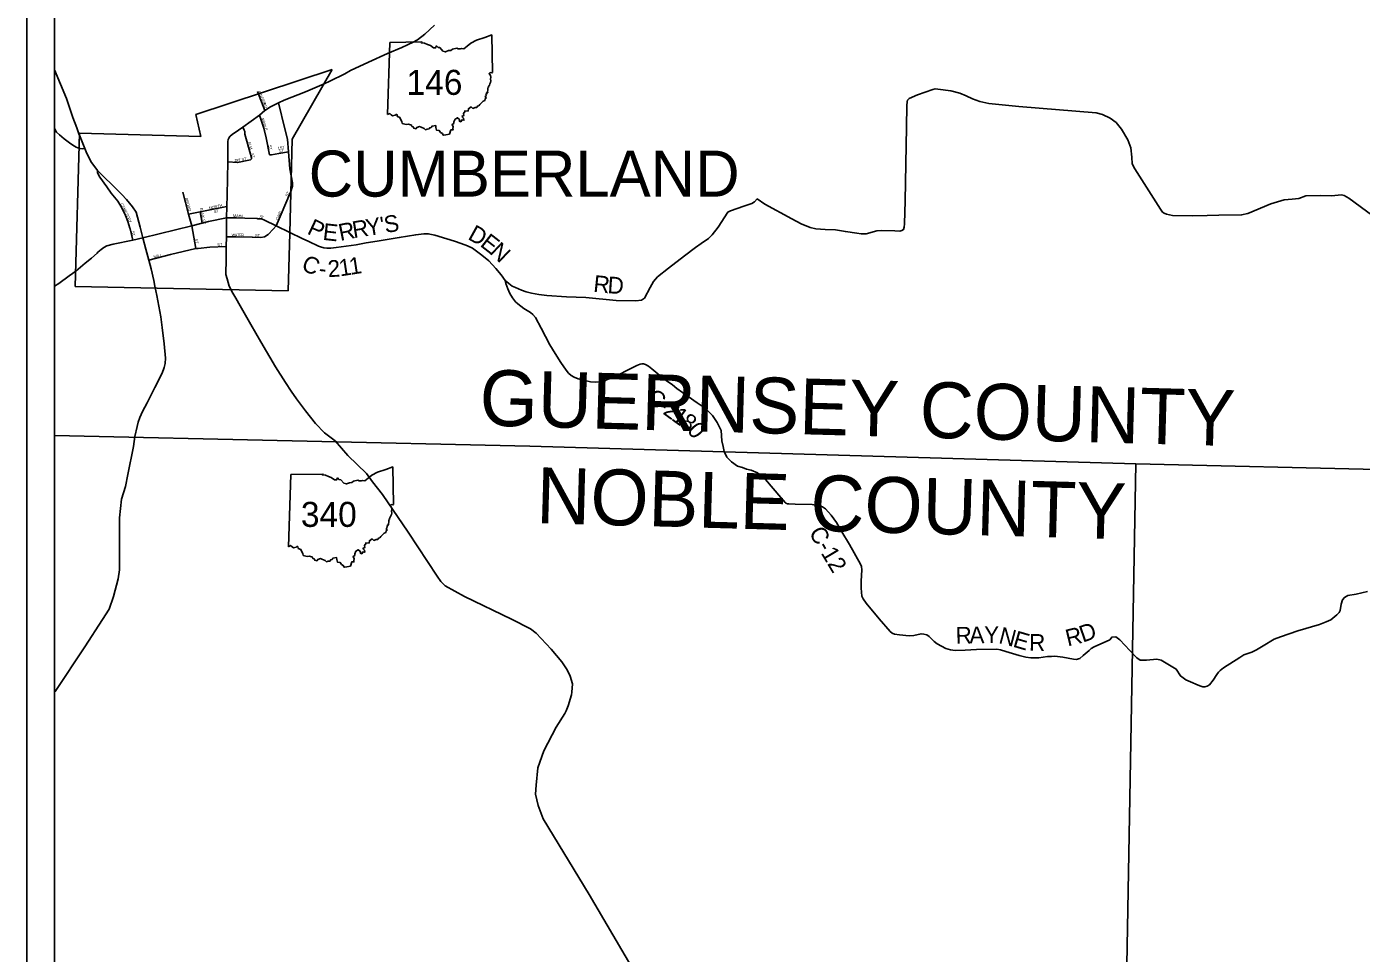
# Model space of a CAD drawing. Extents: x -452339 to 6403467, y -1 to 1814750.
# Drawn here: x -403540 to -379658, y 1620054 to 1636629 of the extents above; entities that cross this region are included whole.
import ezdxf

# ---------------------------------------------------------------- set-up
doc = ezdxf.new("R2010")
doc.units = 0
for name, color, linetype in [('Default', 7, 'Continuous'), ('GM_X_Adjacent_County_Text', 7, 'Continuous'), ('GM_X_County', 7, 'Continuous'), ('GM_X_County_Road', 7, 'Continuous'), ('GM_X_County_ROW', 7, 'Continuous'), ('GM_X_Minor_Lake', 7, 'Continuous'), ('GM_X_Minor_River', 7, 'Continuous'), ('GM_X_Minor_River_Text', 7, 'Continuous'), ('GM_X_Section_Text', 7, 'Continuous')]:
    doc.layers.add(name, color=color, linetype=linetype)

msp = doc.modelspace()

# ---------------------------------------------------------------- linework, layer by layer
at = {"layer": 'Default'}
for p, q in [((-403040, 1603979), (-403040, 1661357)), ((-397082, 1635056), (-397041, 1636348)), ((-398854, 1627328), (-398813, 1628619))]:
    msp.add_line(p, q, dxfattribs=at)
msp.add_lwpolyline([(-403540, 1661857), (-345163, 1661857), (-345163, 1603479), (-403540, 1603479)], close=True, dxfattribs=at)
for points in [[(-397041, 1636348), (-396468, 1636356), (-396477, 1636340), (-396423, 1636337), (-396366, 1636309), (-396317, 1636292), (-396258, 1636251), (-396222, 1636251), (-396207, 1636285), (-396180, 1636259), (-396148, 1636255), (-396092, 1636193), (-396046, 1636179), (-395990, 1636201), (-395950, 1636204), (-395919, 1636225), (-395841, 1636243), (-395819, 1636232), (-395777, 1636235), (-395756, 1636242), (-395720, 1636235), (-395656, 1636282), (-395591, 1636337), (-395489, 1636390), (-395339, 1636439), (-395219, 1636483), (-395202, 1635813)], [(-395202, 1635813), (-395219, 1635804), (-395247, 1635808), (-395265, 1635790), (-395242, 1635758), (-395232, 1635725), (-395241, 1635689), (-395232, 1635659), (-395238, 1635633), (-395255, 1635608), (-395261, 1635584), (-395276, 1635559), (-395275, 1635545), (-395289, 1635534), (-395286, 1635492), (-395293, 1635469), (-395291, 1635449), (-395314, 1635444), (-395308, 1635427), (-395323, 1635414), (-395320, 1635392), (-395336, 1635378), (-395320, 1635350), (-395333, 1635341), (-395344, 1635307), (-395373, 1635300), (-395430, 1635238), (-395451, 1635214), (-395474, 1635208), (-395487, 1635184), (-395515, 1635184), (-395559, 1635167), (-395586, 1635196), (-395635, 1635161), (-395641, 1635120), (-395702, 1635122), (-395700, 1635101), (-395713, 1635096), (-395726, 1635075), (-395719, 1635039), (-395748, 1635030), (-395744, 1635009), (-395725, 1634996), (-395717, 1634956), (-395748, 1634964), (-395773, 1634930), (-395799, 1634938), (-395791, 1634966), (-395834, 1635001), (-395875, 1634974), (-395897, 1634929), (-395897, 1634899), (-395928, 1634881), (-395908, 1634840), (-395912, 1634811), (-395911, 1634783), (-395950, 1634784), (-395973, 1634710)], [(-394980, 1632091), (-394910, 1632034), (-394855, 1631990), (-394796, 1631963), (-394688, 1631915), (-394605, 1631886), (-394505, 1631861), (-394376, 1631842), (-394235, 1631824), (-393879, 1631797), (-393536, 1631784), (-392994, 1631731), (-392637, 1631723), (-392539, 1631738), (-392486, 1631775), (-392386, 1631964), (-392325, 1632073), (-392252, 1632156), (-392057, 1632308), (-391766, 1632529), (-391573, 1632682), (-391468, 1632751), (-391341, 1632842), (-391271, 1632905), (-391169, 1633041), (-390994, 1633313), (-390946, 1633337), (-390708, 1633422), (-390567, 1633468), (-390519, 1633498), (-390470, 1633549), (-390333, 1633455), (-389848, 1633194), (-389684, 1633105), (-389519, 1633036), (-389419, 1633014), (-389249, 1633003), (-389068, 1632994), (-388888, 1632963), (-388687, 1632936), (-388607, 1632925), (-388517, 1632926), (-388330, 1632978), (-388238, 1632981), (-388004, 1632978), (-387918, 1632973), (-387881, 1632984), (-387849, 1632999), (-387838, 1633041), (-387831, 1633105), (-387822, 1633512), (-387795, 1634833), (-387788, 1635222), (-387785, 1635286), (-387778, 1635316), (-387746, 1635347), (-387599, 1635410), (-387325, 1635507), (-387281, 1635516), (-387233, 1635513), (-387005, 1635481), (-386840, 1635440), (-386729, 1635392), (-386614, 1635338), (-386482, 1635292), (-386321, 1635257), (-385784, 1635201), (-384400, 1635087), (-384286, 1635061), (-384149, 1634993), (-384047, 1634917), (-383947, 1634797), (-383833, 1634605), (-383783, 1634465), (-383762, 1634298), (-383757, 1634174), (-383712, 1634084), (-383253, 1633366), (-383218, 1633313), (-383187, 1633295), (-383145, 1633276), (-383039, 1633254), (-382673, 1633247), (-382417, 1633253), (-382209, 1633258), (-381801, 1633263), (-381686, 1633287), (-381275, 1633459), (-381040, 1633533), (-380896, 1633542), (-380777, 1633554), (-380650, 1633603), (-380382, 1633611), (-380194, 1633603), (-380012, 1633619), (-379964, 1633611), (-379883, 1633563), (-379247, 1633100)], [(-395973, 1634710), (-396040, 1634696), (-396086, 1634687), (-396102, 1634721), (-396136, 1634739), (-396157, 1634772), (-396205, 1634777), (-396216, 1634824), (-396221, 1634861), (-396287, 1634852), (-396304, 1634829), (-396327, 1634823), (-396341, 1634800), (-396372, 1634798), (-396406, 1634787), (-396428, 1634809), (-396484, 1634833), (-396509, 1634844), (-396561, 1634826), (-396572, 1634804), (-396613, 1634814), (-396623, 1634838), (-396648, 1634845), (-396653, 1634871), (-396707, 1634885), (-396748, 1634879), (-396820, 1634900), (-396825, 1634934), (-396849, 1634975), (-396862, 1635004), (-396907, 1635025), (-396917, 1635060), (-396931, 1635059), (-396945, 1635045), (-396996, 1635038), (-397016, 1635052), (-397044, 1635076), (-397082, 1635056)], [(-398833, 1632951), (-398612, 1632840), (-398494, 1632785), (-398320, 1632706), (-398283, 1632689), (-398224, 1632673), (-398169, 1632667), (-398096, 1632668), (-398005, 1632678), (-397644, 1632730), (-397466, 1632761), (-397270, 1632792), (-396873, 1632856), (-396578, 1632909), (-396434, 1632926), (-396353, 1632926), (-396234, 1632903), (-396020, 1632834), (-395885, 1632792), (-395768, 1632754), (-395655, 1632708), (-395562, 1632665), (-395493, 1632616), (-395398, 1632542), (-395272, 1632439), (-395144, 1632304), (-395052, 1632192), (-394980, 1632091)], [(-391057, 1629033), (-391076, 1629122), (-391099, 1629224), (-391112, 1629405), (-391182, 1629548), (-391268, 1629675), (-391363, 1629769), (-391434, 1629828), (-391545, 1629902), (-391706, 1630014), (-391909, 1630160), (-391985, 1630226), (-392095, 1630300), (-392244, 1630417), (-392352, 1630510), (-392414, 1630556), (-392464, 1630587), (-392502, 1630601), (-392532, 1630601), (-392564, 1630594), (-392623, 1630570), (-392691, 1630535), (-392787, 1630486), (-392951, 1630404), (-393117, 1630330), (-393222, 1630291), (-393284, 1630276), (-393354, 1630270), (-393451, 1630276), (-393553, 1630298), (-393673, 1630331), (-393745, 1630358), (-393798, 1630392), (-393843, 1630430), (-393884, 1630484), (-393981, 1630622), (-394083, 1630785), (-394177, 1630940), (-394331, 1631236), (-394436, 1631427), (-394481, 1631481), (-394523, 1631516), (-394645, 1631591), (-394752, 1631671), (-394793, 1631709), (-394849, 1631779), (-394895, 1631854), (-394929, 1631938), (-394969, 1632037), (-394980, 1632091)], [(-391057, 1629033), (-391010, 1628931), (-390928, 1628847), (-390821, 1628771), (-390733, 1628742), (-390658, 1628713), (-390578, 1628696), (-390465, 1628651), (-390404, 1628604), (-390321, 1628528), (-390047, 1628210), (-389968, 1628121), (-389953, 1628108), (-389927, 1628096), (-389901, 1628096), (-389787, 1628090), (-389487, 1628080), (-389357, 1628060), (-389298, 1628039), (-389248, 1628004), (-389142, 1627894), (-389047, 1627761), (-388951, 1627593), (-388815, 1627365), (-388617, 1627016), (-388600, 1626976), (-388597, 1626916), (-388605, 1626711), (-388607, 1626583), (-388604, 1626515), (-388593, 1626445), (-388570, 1626397), (-388521, 1626320), (-388284, 1626040), (-388086, 1625811), (-388051, 1625780), (-388011, 1625762), (-387921, 1625754), (-387751, 1625735), (-387667, 1625740), (-387535, 1625769), (-387487, 1625762), (-387435, 1625749), (-387388, 1625721), (-387358, 1625690), (-387301, 1625629), (-387246, 1625590), (-387093, 1625504), (-387010, 1625480), (-386924, 1625469), (-386746, 1625474), (-386646, 1625484), (-386542, 1625486), (-386179, 1625495), (-386112, 1625484), (-386018, 1625455), (-385783, 1625381), (-385660, 1625352), (-385570, 1625339), (-385426, 1625338), (-385272, 1625361), (-385202, 1625366), (-385144, 1625369), (-384996, 1625351), (-384807, 1625313), (-384759, 1625312), (-384696, 1625329), (-384633, 1625380), (-384530, 1625470), (-384491, 1625507), (-384439, 1625536), (-384155, 1625663), (-384154, 1625665)], [(-398813, 1628619), (-398240, 1628628), (-398249, 1628612), (-398195, 1628609), (-398138, 1628581), (-398089, 1628564), (-398030, 1628523), (-397995, 1628523), (-397980, 1628557), (-397952, 1628531), (-397920, 1628526), (-397864, 1628464), (-397818, 1628451), (-397763, 1628472), (-397722, 1628476), (-397692, 1628497), (-397613, 1628515), (-397591, 1628504), (-397549, 1628506), (-397528, 1628514), (-397492, 1628507), (-397429, 1628554), (-397363, 1628609), (-397261, 1628662), (-397111, 1628711), (-396991, 1628755), (-396974, 1628085)], [(-396974, 1628085), (-396991, 1628076), (-397019, 1628080), (-397037, 1628062), (-397014, 1628030), (-397004, 1627997), (-397013, 1627961), (-397004, 1627930), (-397010, 1627905), (-397027, 1627880), (-397033, 1627856), (-397048, 1627831), (-397047, 1627817), (-397061, 1627806), (-397058, 1627764), (-397065, 1627741), (-397063, 1627721), (-397086, 1627715), (-397081, 1627699), (-397095, 1627686), (-397092, 1627664), (-397108, 1627650), (-397092, 1627622), (-397105, 1627613), (-397116, 1627579), (-397145, 1627572), (-397203, 1627509), (-397223, 1627486), (-397246, 1627480), (-397259, 1627455), (-397288, 1627455), (-397331, 1627439), (-397359, 1627467), (-397407, 1627433), (-397413, 1627392), (-397474, 1627394), (-397472, 1627373), (-397486, 1627367), (-397498, 1627347), (-397491, 1627311), (-397520, 1627301), (-397516, 1627281), (-397498, 1627268), (-397490, 1627228), (-397520, 1627236), (-397545, 1627202), (-397571, 1627210), (-397563, 1627238), (-397606, 1627273), (-397648, 1627245), (-397669, 1627201), (-397669, 1627171), (-397700, 1627153), (-397680, 1627111), (-397684, 1627082), (-397684, 1627055), (-397722, 1627056), (-397745, 1626982)], [(-397745, 1626982), (-397812, 1626968), (-397858, 1626959), (-397875, 1626993), (-397908, 1627011), (-397930, 1627044), (-397977, 1627049), (-397988, 1627096), (-397994, 1627133), (-398059, 1627124), (-398076, 1627101), (-398100, 1627095), (-398113, 1627071), (-398145, 1627070), (-398178, 1627058), (-398201, 1627081), (-398256, 1627104), (-398281, 1627116), (-398333, 1627098), (-398344, 1627076), (-398385, 1627086), (-398395, 1627110), (-398420, 1627117), (-398426, 1627143), (-398479, 1627157), (-398520, 1627151), (-398592, 1627172), (-398597, 1627206), (-398622, 1627247), (-398634, 1627276), (-398680, 1627297), (-398689, 1627331), (-398704, 1627330), (-398717, 1627317), (-398768, 1627310), (-398788, 1627324), (-398817, 1627348), (-398854, 1627328)], [(-384154, 1625665), (-384124, 1625707), (-384053, 1625716), (-383980, 1625664), (-383797, 1625468), (-383676, 1625341), (-383614, 1625298), (-383502, 1625298), (-383317, 1625315), (-383241, 1625298), (-383147, 1625244), (-382968, 1625137), (-382896, 1625016), (-382797, 1624948), (-382670, 1624890), (-382616, 1624869), (-382549, 1624836), (-382495, 1624819), (-382457, 1624818), (-382415, 1624835), (-382376, 1624859), (-382311, 1624941), (-382241, 1625040), (-382211, 1625083), (-382186, 1625115), (-382123, 1625160), (-381834, 1625348), (-381757, 1625393), (-381614, 1625440), (-381532, 1625481), (-381352, 1625589), (-381275, 1625636), (-381219, 1625671), (-381106, 1625717), (-380794, 1625823), (-380408, 1625936), (-380285, 1625982), (-380205, 1626022), (-380095, 1626108), (-380056, 1626149), (-380034, 1626185), (-380018, 1626302), (-379992, 1626380), (-379960, 1626421), (-379899, 1626452), (-379747, 1626481), (-379546, 1626525)]]:
    msp.add_lwpolyline(points, dxfattribs=at)
at = {"layer": 'GM_X_County_Road'}
for points in [[(-398114, 1635658), (-397845, 1635785), (-397746, 1635847), (-397421, 1635995), (-397081, 1636148), (-396830, 1636256), (-396624, 1636353), (-396548, 1636392), (-396417, 1636498), (-396242, 1636658)], [(-402600, 1634695), (-402643, 1634820), (-402714, 1635003), (-402825, 1635344), (-403040, 1635856)], [(-399898, 1634672), (-399864, 1634699), (-399749, 1634781), (-399672, 1634831), (-399373, 1635046), (-399279, 1635129), (-399179, 1635195), (-399034, 1635265), (-398931, 1635316), (-398554, 1635464), (-398218, 1635608), (-398114, 1635658)], [(-401464, 1632852), (-401464, 1632852), (-401510, 1633046), (-401583, 1633311), (-401646, 1633410), (-401756, 1633541), (-401836, 1633625), (-401988, 1633778), (-402180, 1633964), (-402273, 1634060), (-402319, 1634121), (-402379, 1634203), (-402427, 1634291), (-402475, 1634394), (-402502, 1634450), (-402598, 1634689), (-402600, 1634695)], [(-399965, 1633212), (-399958, 1633416), (-399951, 1633615), (-399938, 1634210), (-399939, 1634573), (-399933, 1634613), (-399925, 1634637), (-399905, 1634666), (-399898, 1634672)], [(-401464, 1632852), (-400587, 1633065), (-400425, 1633112), (-400398, 1633118), (-400284, 1633147), (-399965, 1633212)], [(-399965, 1633212), (-399965, 1632870), (-399968, 1632698), (-399970, 1632559), (-399969, 1632462)], [(-402266, 1632594), (-402205, 1632642), (-402158, 1632678), (-402104, 1632707), (-401990, 1632741), (-401641, 1632810), (-401464, 1632852)], [(-401246, 1631990), (-401266, 1632087), (-401315, 1632298), (-401355, 1632452), (-401407, 1632652), (-401464, 1632852)], [(-403040, 1631989), (-402965, 1632036), (-402779, 1632174), (-402663, 1632258), (-402492, 1632402), (-402383, 1632491), (-402282, 1632581), (-402266, 1632594)], [(-399969, 1632462), (-399969, 1632424), (-399974, 1632250), (-399974, 1632194), (-399953, 1632118), (-399915, 1631987)], [(-401606, 1629296), (-401565, 1629475), (-401547, 1629555), (-401517, 1629640), (-401467, 1629749), (-401385, 1629903), (-401245, 1630175), (-401118, 1630432), (-401081, 1630532), (-401061, 1630604), (-401058, 1630701), (-401078, 1630957), (-401113, 1631250), (-401141, 1631441), (-401211, 1631820), (-401246, 1631990)], [(-399915, 1631987), (-399914, 1631984), (-399869, 1631891), (-399800, 1631771), (-399721, 1631636), (-399528, 1631303), (-399348, 1630995), (-399088, 1630547), (-398908, 1630262), (-398808, 1630109), (-398713, 1629974), (-398553, 1629759), (-398372, 1629532), (-398211, 1629366), (-398019, 1629219)], [(-403040, 1624724), (-403031, 1624740), (-402499, 1625536), (-402183, 1626023), (-402067, 1626211), (-401989, 1626439), (-401905, 1626754), (-401880, 1626914), (-401878, 1627321), (-401879, 1627842), (-401846, 1628178), (-401775, 1628404), (-401732, 1628617), (-401631, 1629119), (-401606, 1629296)], [(-398019, 1629219), (-397791, 1628960), (-397458, 1628640), (-397354, 1628489), (-397171, 1628262), (-396714, 1627585), (-396195, 1626800), (-396132, 1626707), (-396050, 1626626), (-395706, 1626439), (-394863, 1626029), (-394525, 1625860), (-394422, 1625778), (-394154, 1625492), (-393965, 1625267), (-393869, 1625128), (-393817, 1625013), (-393771, 1624874), (-393786, 1624723), (-393790, 1624680), (-393849, 1624482), (-393887, 1624393), (-393909, 1624343), (-394066, 1624098), (-394287, 1623675), (-394391, 1623374), (-394426, 1623063), (-394436, 1622903), (-394387, 1622700), (-394300, 1622460), (-393477, 1621106), (-392730, 1619837)]]:
    msp.add_lwpolyline(points, dxfattribs=at)
at = {"layer": 'GM_X_County_ROW'}
msp.add_lwpolyline([(-402653, 1634477), (-402686, 1634493), (-402752, 1634533), (-402867, 1634625), (-402956, 1634698), (-403006, 1634745), (-403030, 1634782), (-403040, 1634812)], dxfattribs=at)
at = {"layer": 'GM_X_Minor_Lake'}
for points in [[(-399279, 1635129), (-399412, 1635468)], [(-399076, 1633066), (-398815, 1633683), (-398783, 1633779), (-398783, 1633839), (-398831, 1634088), (-398856, 1634389), (-398874, 1634617), (-398918, 1634805), (-399034, 1635265)], [(-399194, 1634336), (-399254, 1634643), (-399299, 1634817), (-399373, 1635046)], [(-399534, 1634245), (-399519, 1634264), (-399520, 1634283), (-399550, 1634391), (-399611, 1634621), (-399634, 1634710), (-399638, 1634752), (-399651, 1634781), (-399672, 1634831)], [(-402502, 1634450), (-402538, 1634445), (-402588, 1634453), (-402623, 1634461), (-402653, 1634477)], [(-399194, 1634336), (-399162, 1634340), (-399026, 1634362), (-398856, 1634389)], [(-401692, 1633023), (-401728, 1633147), (-401775, 1633251), (-401839, 1633388), (-401909, 1633510), (-402029, 1633653), (-402108, 1633765), (-402232, 1633937), (-402273, 1634015), (-402273, 1634060)], [(-399938, 1634210), (-399767, 1634199), (-399534, 1634245)], [(-400588, 1633068), (-400643, 1633274), (-400749, 1633669)], [(-400643, 1633274), (-400438, 1633317), (-399958, 1633416)], [(-400398, 1633118), (-400438, 1633317)], [(-399965, 1633212), (-399787, 1633210), (-399638, 1633207), (-399414, 1633196)], [(-399414, 1633196), (-399402, 1633195), (-399340, 1633192), (-399282, 1633169), (-399076, 1633066)], [(-401641, 1632810), (-401690, 1633016), (-401692, 1633023)], [(-400516, 1632659), (-400587, 1633065), (-400588, 1633068)], [(-399965, 1632870), (-399797, 1632868), (-399506, 1632862)], [(-399506, 1632862), (-399499, 1632862), (-399353, 1632860), (-399285, 1632871), (-399221, 1632914), (-399129, 1633005), (-399076, 1633066)], [(-399076, 1633066), (-398833, 1632951)], [(-401355, 1632452), (-400968, 1632555), (-400516, 1632659), (-400503, 1632660), (-400471, 1632664)], [(-400471, 1632664), (-400260, 1632688), (-399968, 1632698)]]:
    msp.add_lwpolyline(points, dxfattribs=at)
at = {"layer": 'GM_X_Minor_River_Text'}
for p, q in [((-400513, 1635059), (-398071, 1635863)), ((-398071, 1635863), (-398789, 1634620)), ((-400426, 1634664), (-400513, 1635059)), ((-402672, 1631980), (-402595, 1634724)), ((-402595, 1634724), (-400426, 1634664)), ((-398789, 1634620), (-398833, 1632937)), ((-398833, 1632937), (-398859, 1631903)), ((-398859, 1631903), (-402672, 1631980))]:
    msp.add_line(p, q, dxfattribs=at)
at = {"layer": 'GM_X_Section_Text'}
for p, q in [((-403040, 1629318), (-394538, 1629126)), ((-394538, 1629126), (-383695, 1628810)), ((-383695, 1628810), (-383932, 1615503)), ((-383695, 1628810), (-378448, 1628686))]:
    msp.add_line(p, q, dxfattribs=at)

# ---------------------------------------------------------------- texts
at = {"layer": 'Default'}
for s, p in [('146', (-396742, 1635410)), ('340', (-398633, 1627682))]:
    msp.add_text(s, height=447.7, dxfattribs=at).set_placement(p)
at = {"layer": 'GM_X_Adjacent_County_Text'}
for s, height, rotation, p in [('CUMBERLAND', 823.7, 0, (-398494, 1633590)), ('GUERNSEY COUNTY', 1000, 358.4232, (-395445, 1629498)), ('NOBLE COUNTY', 1000, 358.4232, (-394429, 1627750))]:
    msp.add_text(s, height=height, rotation=rotation, dxfattribs=at).set_placement(p)
at = {"layer": 'GM_X_County'}
for s, rotation, p in [('P', 334.8716, (-398538, 1632933)), ('E', 353.6707, (-398252, 1632818)), ('R', 11.1712, (-397929, 1632797)), ('R', 9.2551, (-397690, 1632845)), ('Y', 9.2545, (-397447, 1632884)), ("'", 9.2581, (-397187, 1632927)), ('S', 9.253, (-397121, 1632937)), ('D', 330.927, (-395663, 1632837)), ('E', 322.0664, (-395443, 1632716)), ('N', 316.6629, (-395271, 1632583)), ('C', 336.9769, (-398643, 1632284)), ('2', 3.5213, (-398145, 1632148)), ('1', 8.7072, (-397931, 1632162)), ('1', 8.7566, (-397748, 1632190)), ('-', 353.4185, (-398325, 1632163)), ('R', 354.1745, (-393409, 1631889)), ('D', 356.2646, (-393153, 1631863)), ('C', 322.2387, (-392476, 1629944)), ('-', 324.3443, (-392271, 1629786)), ('2', 324.3596, (-392171, 1629714)), ('1', 324.3438, (-392021, 1629606)), ('8', 323.841, (-391871, 1629499)), ('0', 309.7026, (-391736, 1629403)), ('C-12', 300.7441, (-389552, 1627580)), ('D', 19.1785, (-384642, 1625610)), ('R', 1.374, (-386914, 1625590)), ('A', 1.3698, (-386668, 1625596)), ('Y', 0.2732, (-386405, 1625603)), ('N', 345.6881, (-386161, 1625606)), ('E', 343.7773, (-385908, 1625542)), ('R', 359.2429, (-385605, 1625466)), ('R', 13.5478, (-384911, 1625543))]:
    msp.add_text(s, height=300, rotation=rotation, dxfattribs=at).set_placement(p)
at = {"layer": 'GM_X_Minor_River'}
for s, rotation, p in [('SINGER', 293.4993, (-399406, 1635471)), ('RD', 293.9614, (-399314, 1635255)), ('MAPLE', 287.2778, (-399344, 1634990)), ('ELM', 285.9444, (-399586, 1634563)), ('ST', 10.6213, (-399689, 1634226)), ('ST', 288.4262, (-399529, 1634361)), ('ST', 284.9242, (-399216, 1634506)), ('1ST', 9.8702, (-399044, 1634429)), ('ST', 7.12, (-399023, 1634375)), ('1', 354.7773, (-399830, 1634217)), ('S', 357.0818, (-399798, 1634214)), ('T', 11.9171, (-399748, 1634214)), ('BROAD', 285.4621, (-400708, 1633560)), ('ST', 66.8023, (-398868, 1633583)), ('CEMETERY', 295.8879, (-401866, 1633460)), ('BANK ST', 280.7367, (-400439, 1633383)), ('NORTH', 12.0102, (-400274, 1633359)), ('ST', 11.3113, (-400187, 1633293)), ('CARL', 68.1986, (-399039, 1633165)), ('MAIN', 358.4498, (-399849, 1633223)), ('S', 352.3259, (-399378, 1633206)), ('T', 346.8784, (-399345, 1633201)), ('ST', 284.9242, (-401667, 1632966)), ('W', 357.1242, (-399876, 1632880)), ('A', 358.3602, (-399817, 1632877)), ('T', 359.7134, (-399772, 1632876)), ('E', 359.9956, (-399736, 1632876)), ('R', 359.9941, (-399701, 1632876)), ('ST', 0, (-399454, 1632871)), ('ST', 280.6135, (-400532, 1632833)), ('ST', 3.5738, (-400127, 1632704)), ('MILL', 13.6288, (-401264, 1632488))]:
    msp.add_text(s, height=50, rotation=rotation, dxfattribs=at).set_placement(p)

doc.saveas('drawing.dxf')
